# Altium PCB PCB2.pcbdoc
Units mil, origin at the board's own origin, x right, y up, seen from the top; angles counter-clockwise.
Board outline 1840 x 1230 mil, 2 copper layers (Top Layer, Bottom Layer), stack 62.2 mil thick; 30 components, 19 nets, 78 pads, 15 vias.
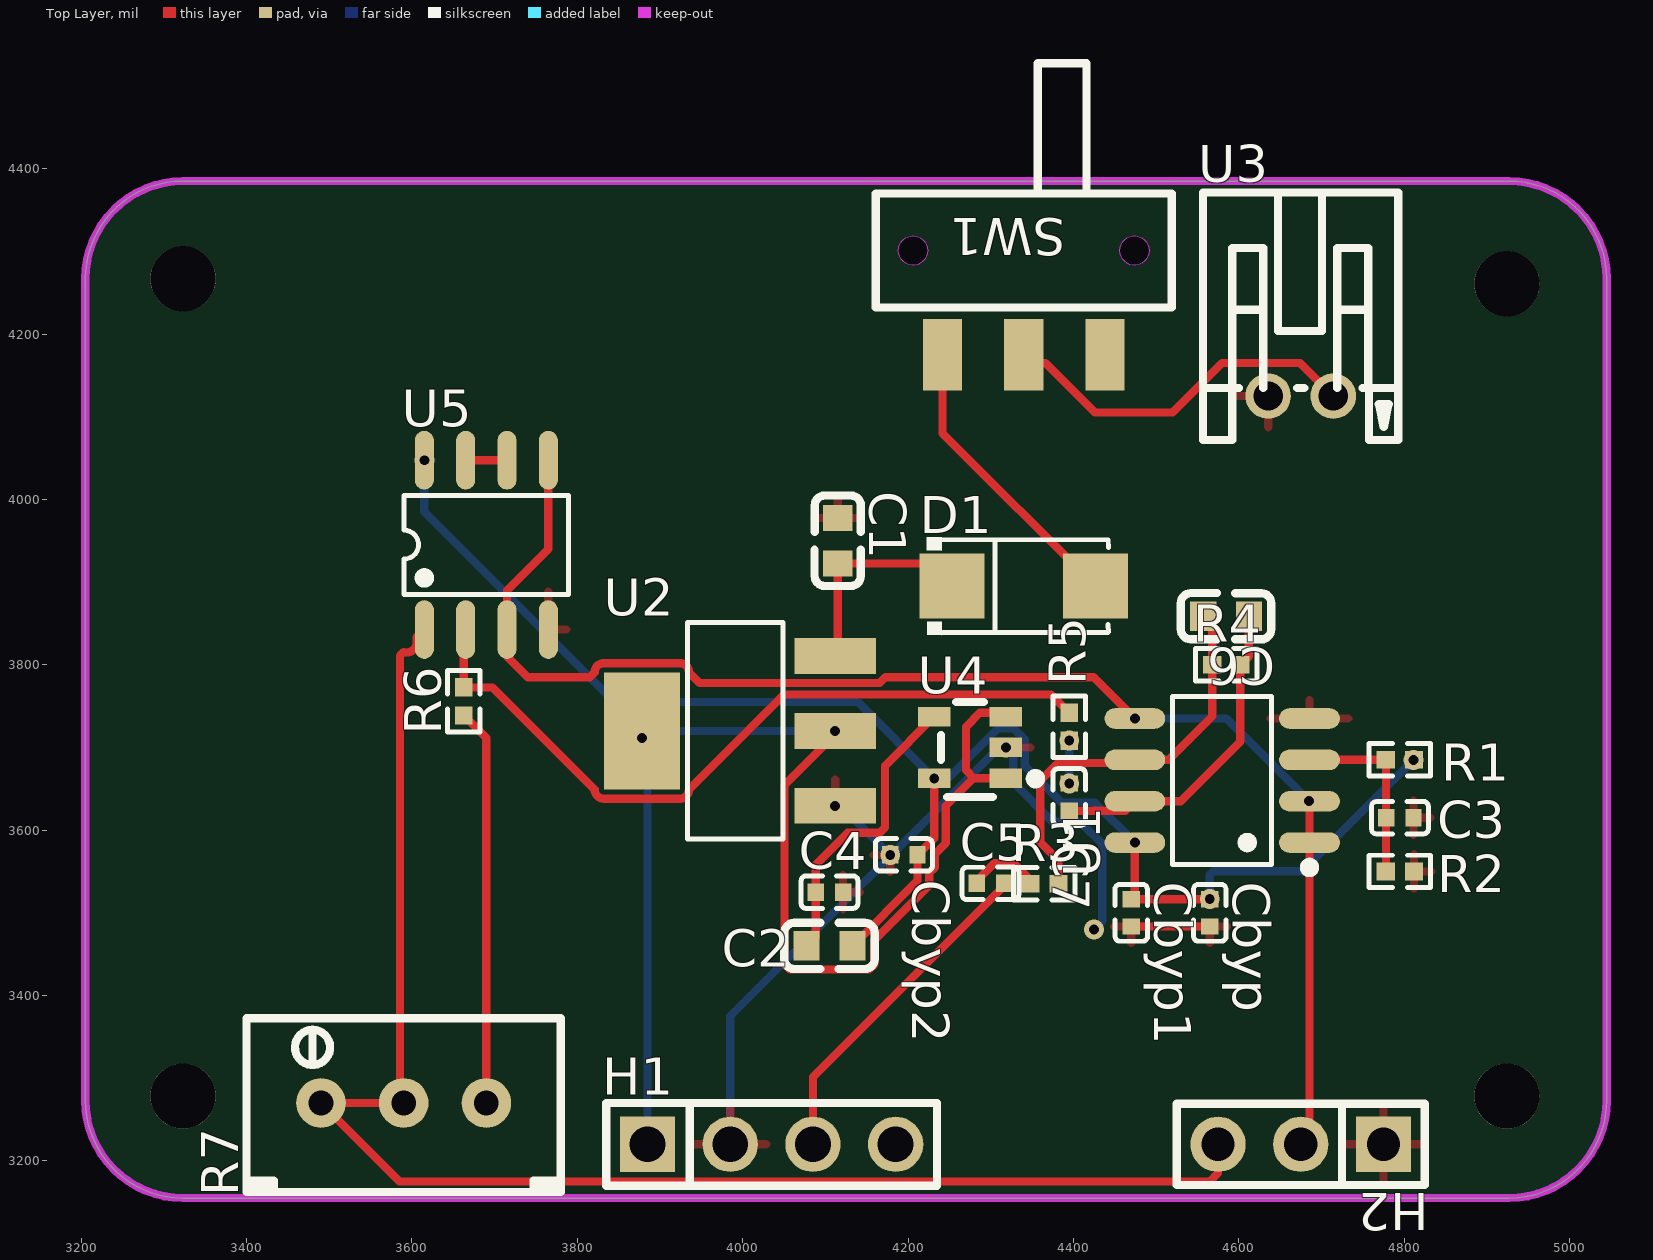
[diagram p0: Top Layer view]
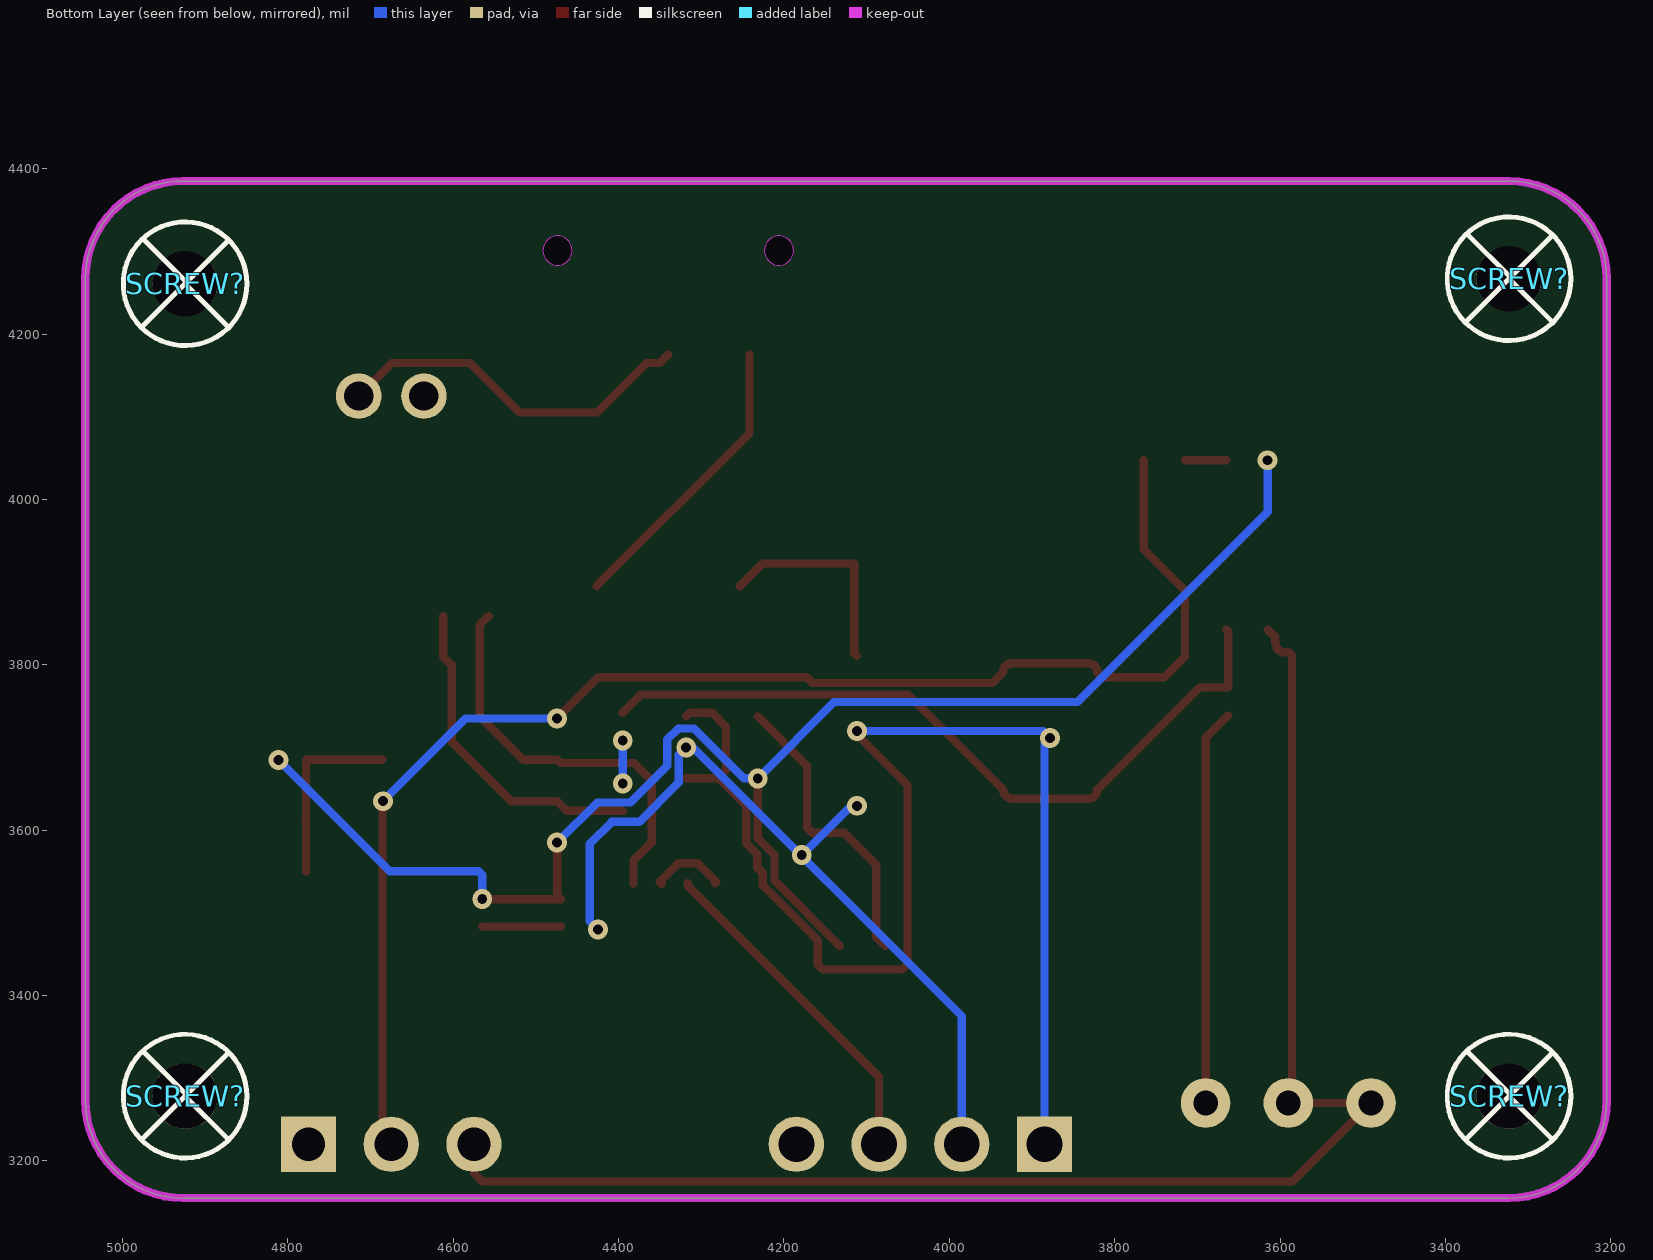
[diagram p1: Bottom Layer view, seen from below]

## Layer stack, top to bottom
Top Solder Mask Layer: solder mask 0.4, Dk 3.3
Top Layer: signal copper 1.4
Dielectric1: surface 59.4, FR4, Dk 4.5
Bottom Layer: signal copper 1.4
Bottom Solder Mask Layer: solder mask 0.4, Dk 3.3

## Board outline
3323.1,4385 ccw(c3323.1,4266.9) 3205,4266.9 3205,3273.1 ccw(c3323.1,3273.1) 3323.1,3155 4926.9,3155 ccw(c4926.9,3273.1) 5045,3273.1 5045,4266.9 ccw(c4926.9,4266.9) 4926.9,4385

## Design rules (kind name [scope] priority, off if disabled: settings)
BoardOutlineClearance copperThickness1oz [All] p0: genericclearance=10 ignorepadtopadclearanceinfootprint=FALSE except(0: Arc-SplitContinuation Track-SplitContinuation SMDPad-SplitContinuation THPad-SplitContinuation Via-SplitContinuation Fill-SplitContinuation Poly-SplitContinuation Region-SplitContinuation Text-SplitContinuation)
BoardOutlineClearance copperThickness2oz [All] p0: genericclearance=10 ignorepadtopadclearanceinfootprint=FALSE except(0: Arc-SplitContinuation Track-SplitContinuation SMDPad-SplitContinuation THPad-SplitContinuation Via-SplitContinuation Fill-SplitContinuation Poly-SplitContinuation Region-SplitContinuation Text-SplitContinuation)
BoardOutlineClearance otherClearance [All] p0: genericclearance=10 ignorepadtopadclearanceinfootprint=FALSE except(0: Arc-SplitContinuation Track-SplitContinuation SMDPad-SplitContinuation THPad-SplitContinuation Via-SplitContinuation Fill-SplitContinuation Poly-SplitContinuation Region-SplitContinuation Text-SplitContinuation)
Clearance copperThickness1oz [All] p1: gap=7 ignorepadtopadclearanceinfootprint=FALSE
Clearance copperThickness2oz [All] p1: gap=7 ignorepadtopadclearanceinfootprint=FALSE
Clearance otherClearance [All] p1: gap=7 ignorepadtopadclearanceinfootprint=FALSE
DiffPairsRouting differentialPair [All] p1: maxuncoupledlength=10 minlimit=6 maxlimit=Infinity mostfreqgap=6 toplayer_minwidth=5 toplayer_prefwidth=10 toplayer_maxwidth=100 bottomlayer_minwidth=5 bottomlayer_prefwidth=10 bottomlayer_maxwidth=100
PasteMaskExpansion pasteMaskExpansion [All] p1: expansion=0
PlaneConnect innerPlane [All] p1: planeconnectstyle=Relief reliefexpansion=20 reliefentries=4 reliefconductorwidth=10 reliefairgap=10
PolygonConnect copperRegion [All] p1: connectstyle=Relief reliefentries=4 reliefconductorwidth=10 polygonreliefangle="90 Angle" airgapwidth=10
RoutingVias viaSize [All] p1: viastyle="Through Hole" holewidth=12.0078 minholewidth=11.811 maxholewidth=248.0314 width=12.0078 minwidth=11.811 maxwidth=248.0314
SolderMaskExpansion solderMaskExpansion [IsVia] p1: useseparateexpansions=TRUE expansion=-1000 expansionbottom=-1000
SolderMaskExpansion solderMaskExpansion [All] p2: useseparateexpansions=TRUE expansion=2 expansionbottom=2
Width copperThickness1oz [All] p1: maxlimit=100 minlimit=5 preferedwidth=10
Width copperThickness2oz [All] p1: maxlimit=100 minlimit=8 preferedwidth=10

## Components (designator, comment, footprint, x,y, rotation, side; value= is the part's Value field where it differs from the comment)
C1 "10uF" C0603#1 4115,3950 r270 top
C2 "10uF" C0603#1 4105,3460 r180 top
C3 "100nF" C0402#1 4795,3615 r0 top
C4 "10nF" C0402#1 4105,3525 r0 top
C5 "1uF" C0402#2 4299.7,3535.6 r0 top
C6 "100pF" C0603#2 4584.7,3858.7 r180 top
C7 "1uF" C0402#1 4395,3640 r270 top
Cbyp "100nF" C0402#1 4565,3500 r270 top
Cbyp1 "100nF" C0402#1 4470,3500 r270 top
Cbyp2 "100nF" C0402#1 4195,3570 r180 top
D1 "SS34" SMA_L4.3-W2.6-LS5.2-RD 4340,3895 r0 top
H1 "B-2100S04P-A110" HDR-TH_4P-P2.54-V-M 4035,3220 r0 top
H2 "PZ254V-11-03P" HDR-TH_3P-P2.54-V-M_PZ254V-11-03P 4675,3220 r180 top
R1 "10kΩ" R0402 4795,3685 r180 top
R2 "10kΩ" R0402 4795,3550 r180 top
R3 "1kΩ" R0402 4365,3535 r0 top
R4 "10kΩ" R0402 4585,3800 r0 top
R5 "1kΩ" R0402 4395,3725 r90 top
R6 "1kΩ" R0402 3662.8,3755.6 r90 top
R7 "100kΩ" RES-ADJ-TH_3296W 3590,3270 r90 top
SCREW? "" Screw-Hole-M2 3323.1,4266.9 r180 bottom
SCREW? "" Screw-Hole-M2 3323.1,3278.3 r180 bottom
SCREW? "" Screw-Hole-M2 4924.4,3278.3 r180 bottom
SCREW? "" Screw-Hole-M2 4924.4,4260.8 r180 bottom
SW1 "MST-12D18G4 SPDT Slide Switch" SW-SMD_MST-12D18G4-SPDT-SLIDE-SWITCH 4340,4175 r180 top
U1 "MCP6002DRG" SOP-8_L4.9-W3.9-P1.27-LS6.0-BL 4580,3660 r90 top
U2 "AMS1117-5.0" SOT-223-3_L6.5-W3.4-P2.30-LS7.0-BR 3995,3720 r0 top
U3 "S2B-PH-K-S-GW" CONN-TH_S2B-PH-K-S-GW 4675,4125 r0 top
U4 "AP2112K-3.3TRG1" SOT-23-5_L2.9-W1.6-P0.95-LS2.8-BR 4275,3700 r0 top
U5 "MCP6002-I/SN" SOIC-8_L4.9-W3.9-P1.27-LS6.0-BL 3690,3945 r0 top

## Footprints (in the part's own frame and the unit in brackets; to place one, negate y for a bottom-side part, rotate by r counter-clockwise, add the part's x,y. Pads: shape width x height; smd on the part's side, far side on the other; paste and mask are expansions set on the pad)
C0402#1 [mil]
  rect 19.7x21.3 smd: 1(-16.5,0) 2(16.5,0)
  silkscreen extent -34,-20 34,20
C0402#2 [mil]
  rect 19.7x21.3 smd: 1(-16.5,0) 2(16.6,0)
  silkscreen extent -34,-20 34,20
C0603#1 [mil]
  rect 31.5x35.4 smd: 1(-27.6,0) 2(27.6,0)
  silkscreen extent -55,-28 55,28
C0603#2 [mil]
  rect 31.5x35.4 smd: 1(-27.5,0) 2(27.6,0)
  silkscreen extent -55,-28 55,28
CONN-TH_S2B-PH-K-S-GW [mil]
  round 55.1 hole 35.4: 1(39.4,0) 2(-39.4,0)
  silkscreen extent -118,-53 118,246
HDR-TH_3P-P2.54-V-M_PZ254V-11-03P [mil]
  rect 66.9x66.9 hole 40.2: 1(-100,0)
  round 66.9 hole 40.2: 2(0,0) 3(100,0)
  silkscreen extent -150,-49 150,49
HDR-TH_4P-P2.54-V-M [mil]
  rect 66.9x66.9 hole 43.3: 1(-150,0)
  round 66.9 hole 43.3: 2(-50,0) 3(50,0) 4(150,0)
  silkscreen extent -200,-50 200,50
R0402 [mil]
  rect 22.3x21.3 smd paste-3937 mask+2: 1(-17,0) 2(17,0)
  silkscreen extent -37,-20 37,20
RES-ADJ-TH_3296W [mil]
  round 60 hole 30: 1(0,100) 2(0,0) 3(0,-100)
  silkscreen extent -108,-190 102,190
Screw-Hole-M2 [mil]
  round 78.7 hole 78.7: 1(0,0)
  silkscreen extent -75,-75 75,75
SMA_L4.3-W2.6-LS5.2-RD [mil]
  rect 78.7x78.7 smd: 1(-86.6,0) 2(86.6,0)
  silkscreen extent -117,-59 102,59
SOIC-8_L4.9-W3.9-P1.27-LS6.0-BL [mil]
  oval 23.1x70.9 smd paste+0 mask+2: 1(-75,-102.4) 2(-25,-102.4) 3(25,-102.4) 4(75,-102.4) 5(75,102.4) 6(25,102.4) 7(-25,102.4) 8(-75,102.4)
  silkscreen extent -100,-60 100,60
SOP-8_L4.9-W3.9-P1.27-LS6.0-BL [mil]
  oval 24.8x73.4 smd: 1(-75,-105.6) 2(-25,-105.6) 3(25,-105.6) 4(75,-105.6) 5(75,105.6) 6(25,105.6) 7(-25,105.6) 8(-75,105.6)
  silkscreen extent -111,-111 101,60
SOT-23-5_L2.9-W1.6-P0.95-LS2.8-BR [mil]
  rect 39.4x23.6 smd paste+0 mask+2: 1(43.3,-37.4) 2(43.3,0) 3(43.3,37.4) 4(-43.3,37.4) 5(-43.3,-37.4)
  silkscreen extent -35,-60 85,55
SOT-223-3_L6.5-W3.4-P2.30-LS7.0-BR [mil]
  rect 98.4x43.3 smd: 1(116.9,-90.6) 2(116.9,0) 3(116.9,90.6)
  rect 92.1x141.7 smd: 4(-116.9,0)
  silkscreen extent -62,-131 54,131
SW-SMD_MST-12D18G4-SPDT-SLIDE-SWITCH [mil]
  rect 47.2x86.6 smd: 1(-98.4,0) 2(0,0) 3(98.4,0)
  Board Outline Layer lines w0.1: 151.6,-126 151.2,-129.7 150,-133.2 148.2,-136.4 145.7,-139.1 142.7,-141.3 139.3,-142.8 135.7,-143.6 132,-143.6 128.4,-142.8 125,-141.3 122,-139.1 119.5,-136.4 117.7,-133.2 116.5,-129.7 116.1,-126 116.5,-122.3 117.7,-118.8 119.5,-115.6 122,-112.8 125,-110.6 128.4,-109.1 132,-108.4 135.7,-108.4 139.3,-109.1 142.7,-110.6 145.7,-112.8 148.2,-115.6 150,-118.8 151.2,-122.3 151.6,-126 ; -116.1,-126 -116.5,-129.7 -117.7,-133.2 -119.5,-136.4 -122,-139.1 -125,-141.3 -128.4,-142.8 -132,-143.6 -135.7,-143.6 -139.3,-142.8 -142.7,-141.3 -145.7,-139.1 -148.2,-136.4 -150,-133.2 -151.2,-129.7 -151.6,-126 -151.2,-122.3 -150,-118.8 -148.2,-115.6 -145.7,-112.8 -142.7,-110.6 -139.3,-109.1 -135.7,-108.4 -132,-108.4 -128.4,-109.1 -125,-110.6 -122,-112.8 -119.5,-115.6 -117.7,-118.8 -116.5,-122.3 -116.1,-126
  Board Outline Layer region: -116.1,-126 -116.5,-129.7 -117.7,-133.2 -119.5,-136.4 -122,-139.1 -125,-141.3 -128.4,-142.8 -132,-143.6 -135.7,-143.6 -139.3,-142.8 -142.7,-141.3 -145.7,-139.1 -148.2,-136.4 -150,-133.2 -151.2,-129.7 -151.6,-126 -151.2,-122.3 -150,-118.8 -148.2,-115.6 -145.7,-112.8 -142.7,-110.6 -139.3,-109.1 -135.7,-108.4 -132,-108.4 -128.4,-109.1 -125,-110.6 -122,-112.8 -119.5,-115.6 -117.7,-118.8 -116.5,-122.3
  Board Outline Layer region: -116.1,-126 -116.5,-129.7 -117.7,-133.2 -119.5,-136.4 -122,-139.1 -125,-141.3 -128.4,-142.8 -132,-143.6 -135.7,-143.6 -139.3,-142.8 -142.7,-141.3 -145.7,-139.1 -148.2,-136.4 -150,-133.2 -151.2,-129.7 -151.6,-126 -151.2,-122.3 -150,-118.8 -148.2,-115.6 -145.7,-112.8 -142.7,-110.6 -139.3,-109.1 -135.7,-108.4 -132,-108.4 -128.4,-109.1 -125,-110.6 -122,-112.8 -119.5,-115.6 -117.7,-118.8 -116.5,-122.3
  Board Outline Layer region: 151.6,-126 151.2,-129.7 150,-133.2 148.2,-136.4 145.7,-139.1 142.7,-141.3 139.3,-142.8 135.7,-143.6 132,-143.6 128.4,-142.8 125,-141.3 122,-139.1 119.5,-136.4 117.7,-133.2 116.5,-129.7 116.1,-126 116.5,-122.3 117.7,-118.8 119.5,-115.6 122,-112.8 125,-110.6 128.4,-109.1 132,-108.4 135.7,-108.4 139.3,-109.1 142.7,-110.6 145.7,-112.8 148.2,-115.6 150,-118.8 151.2,-122.3
  Board Outline Layer region: 151.6,-126 151.2,-129.7 150,-133.2 148.2,-136.4 145.7,-139.1 142.7,-141.3 139.3,-142.8 135.7,-143.6 132,-143.6 128.4,-142.8 125,-141.3 122,-139.1 119.5,-136.4 117.7,-133.2 116.5,-129.7 116.1,-126 116.5,-122.3 117.7,-118.8 119.5,-115.6 122,-112.8 125,-110.6 128.4,-109.1 132,-108.4 135.7,-108.4 139.3,-109.1 142.7,-110.6 145.7,-112.8 148.2,-115.6 150,-118.8 151.2,-122.3
  Multi-Layer board cut-out: -116.1,-126 -116.5,-129.7 -117.7,-133.2 -119.5,-136.4 -122,-139.1 -125,-141.3 -128.4,-142.8 -132,-143.6 -135.7,-143.6 -139.3,-142.8 -142.7,-141.3 -145.7,-139.1 -148.2,-136.4 -150,-133.2 -151.2,-129.7 -151.6,-126 -151.2,-122.3 -150,-118.8 -148.2,-115.6 -145.7,-112.8 -142.7,-110.6 -139.3,-109.1 -135.7,-108.4 -132,-108.4 -128.4,-109.1 -125,-110.6 -122,-112.8 -119.5,-115.6 -117.7,-118.8 -116.5,-122.3
  Multi-Layer board cut-out: 151.6,-126 151.2,-129.7 150,-133.2 148.2,-136.4 145.7,-139.1 142.7,-141.3 139.3,-142.8 135.7,-143.6 132,-143.6 128.4,-142.8 125,-141.3 122,-139.1 119.5,-136.4 117.7,-133.2 116.5,-129.7 116.1,-126 116.5,-122.3 117.7,-118.8 119.5,-115.6 122,-112.8 125,-110.6 128.4,-109.1 132,-108.4 135.7,-108.4 139.3,-109.1 142.7,-110.6 145.7,-112.8 148.2,-115.6 150,-118.8 151.2,-122.3
  silkscreen extent -179,-352 179,-57

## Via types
v1: diameter 24, hole 12, Top Layer to Bottom Layer, 15 vias

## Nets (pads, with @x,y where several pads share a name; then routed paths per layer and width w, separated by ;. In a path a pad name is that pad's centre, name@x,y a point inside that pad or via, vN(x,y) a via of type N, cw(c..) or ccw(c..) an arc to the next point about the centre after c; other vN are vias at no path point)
3.3V: C2.1 Cbyp1.1 Cbyp2.1 Cbyp.1 R1.1 U1.8 U4.5 U5.8 | length 1898.6
  Top Layer w10: C2.1 4211.5,3539 Cbyp2.1 4231.7,3590.1 v1(4231.7,3662.6) ; v1(4474.4,3585) 4474.4,3520.9 Cbyp1.1 v1(4565,3516.5)
  Bottom Layer w10: v1(3615,4047.4) 3615,3985 3845,3755 4139.3,3755 v1(4231.7,3662.6) 4248.4,3662.6 4308.8,3723 4327.8,3723 4341.3,3709.5 4341.3,3677.7 4385.5,3633.5 4425.8,3633.5 v1(4474.4,3585) ; v1(4565,3516.5) 4565,3545.9 4569.6,3550.4 4677,3550.4 v1(4811.5,3685)
$1N1: SW1.2 U3.1 | length 444.8
  Top Layer w10: SW1.2 4350,4165 4366,4165 4426,4105 4520,4105 4580,4165 4674.4,4165 U3.1
$1N3: D1.2 SW1.3 | length 356.6
  Top Layer w10: SW1.3 4241.6,4080 D1.2
$1N4: C1.2 D1.1 U2.3 | length 262.8
  Top Layer w10: U2.3 4115,3813.6 C1.2 4225.9,3922.4 D1.1
$1N10: C2.2 C4.1 U4.4 | length 364.1
  Top Layer w10: C2.2 4088.5,3471 C4.1 4088.5,3558.5 4126.8,3596.8 4165.7,3596.8 4172.1,3603.2 4172.1,3677.8 U4.4
$1N13: C3.1 R1.2 R2.2 U1.3 | length 228.1
  Top Layer w10: U1.3 R1.2 C3.1@4778,3615.5 ; R2.2 C3.1@4778,3615.5 ; C3.1 C3.1@4778,3615.5
$1N22: C5.1 R3.1 | length 93
  Top Layer w10: C5.1 4281.7,3537 4304.7,3560 4327.8,3560 4350.4,3537.4 R3.1
$1N23: C6.2 R3.2 R4.1 U1.6 | length 499.6
  Top Layer w10: R3.2 4382,3563 4360,3585 4360,3660 4381.2,3681.2 4470.6,3681.2 U1.6 4515,3685 4568,3738 R4.1 4568,3847.8 C6.2
$1N25: C6.1 C7.2 R4.2 U1.7 | length 397.5
  Top Layer w10: C7.2 4462.9,3623.5 U1.7 4530,3635 4602,3707 R4.2 4612.2,3810.2 C6.1
$1N31: R5.2 R6.2 U5.2 | length 923.5
  Top Layer w10: U5.2 3662.8,3840.5 R6.2 3697.5,3772.6 3821,3649.1 ccw(c3832,3649.1) 3832,3638.1 3924.1,3638.1 ccw(c3924.1,3649.1) 3935.1,3649.1 4049.9,3763.9 4373.1,3763.9 R5.2
$1N32: R6.1 R7.3 | length 479.9
  Top Layer w10: R6.1 3690,3711.4 R7.3
$1N48: U5.6 U5.7 | length 50
  Top Layer w10: U5.7 U5.6
+5V: H1.1 U2.2 U2.4 U4.1 U4.3 | length 1591.1
  Top Layer w10: v1(4111.9,3720) 4111.9,3715.9 4050.7,3654.6 4050.7,3437.7 4057.1,3431.3 4152.9,3431.3 4159.3,3437.7 4159.3,3466.9 4225.6,3533.2 4225.6,3548 4232.4,3554.8 4232.4,3571 4245.7,3584.3 4245.7,3629.6 4278.7,3662.6 4280,3662.6 ; U4.1 4280,3662.6 ; U4.3 4313.6,3742.1 4287.1,3742.1 4270,3725 4270,3672.6 4280,3662.6
  Bottom Layer w10: H1.1 3885,3704.7 v1(3878.1,3711.6) 3886.4,3720 v1(4111.9,3720)
GND: C1.1 C3.2 C4.2 Cbyp1.2 Cbyp2.2 Cbyp.2 H1.2 H2.1 R2.1 U1.4 U2.1 U3.2 U4.2 U5.4 | length 1101.1
  Top Layer w10: Cbyp1.2 Cbyp.2
  Bottom Layer w10: H1.2 3985,3375 4310,3700 v1(4318.3,3700) 4327.3,3691 4327.3,3657.7 4375,3610 4408.3,3610 4435,3583.3 4435,3490 v1(4425,3480) ; v1(4111.9,3629.4) 4119,3629.4 v1(4178.5,3570)
IF_ADC_IN: H2.3 R7.1 R7.2 U5.1 | length 1854.7
  Top Layer w10: 3589.95,3815.23 ccw(c3593.5,3826.9) 3605.7,3826.9 3605.7,3833.3 U5.1 ; 3590,3815.3 3585.7,3811 3585.7,3274.3 R7.2 R7.1 3585,3175 4565,3175 4575,3185 H2.3
IF_BANDPASS: C7.1 R5.1 | length 51.8
  Bottom Layer w10: v1(4395,3656.5) v1(4395,3708.3)
IF_OUT_RAW: C5.2 H1.3 | length 411.4
  Top Layer w10: H1.3 4085,3301.3 4316.3,3532.6 C5.2
V_MID: H2.2 U1.1 U1.2 U1.5 U5.3 U5.5 | length 1744.2
  Top Layer w10: U5.5 3765,3940 3715,3890 U5.3 3715,3810 3740,3785 3815.2,3785 3821,3790.9 cw(c3832,3790.9) 3832,3801.9 3924.1,3801.9 cw(c3924.1,3790.9) 3935.1,3790.9 3948.1,3777.9 4165.7,3777.9 4172.8,3785 4424.4,3785 v1(4474.4,3735) ; H2.2 4685.6,3230.6 U1.1 U1.2@4685.6,3634.4 ; v1(4685,3635) U1.2@4685.6,3634.4 ; U1.2 U1.2@4685.6,3634.4
  Bottom Layer w10: v1(4474.4,3735) 4585,3735 v1(4685,3635)
V_TUNE: H1.4
pads on no net: SCREW?.1 SW1.1

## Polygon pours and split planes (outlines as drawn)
GND on Top Layer (solid, remove dead copper, pour order 0): 3000,4520 3000,3000 5690,3000 5690,4520

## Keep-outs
Board Outline Layer:
  lines w10: 3205,4266.9 cw(c3323.1,4266.9) 3323.1,4385 4926.9,4385 ; 3205,4266.9 3205,4266.9 ; 3205,4266.9 3205,3273.1 ccw(c3323.1,3273.1) 3323.1,3155 4926.9,3155 ; 4926.9,3155 4926.9,3155 ; 4926.9,3155 ccw(c4926.9,3273.1) 5045,3273.1 5045,4266.9 ; 4926.9,4385 cw(c4926.9,4266.9) 5045,4266.9 ; 4926.9,4385 4926.9,4385 ; 5045,4266.9 5045,4266.9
